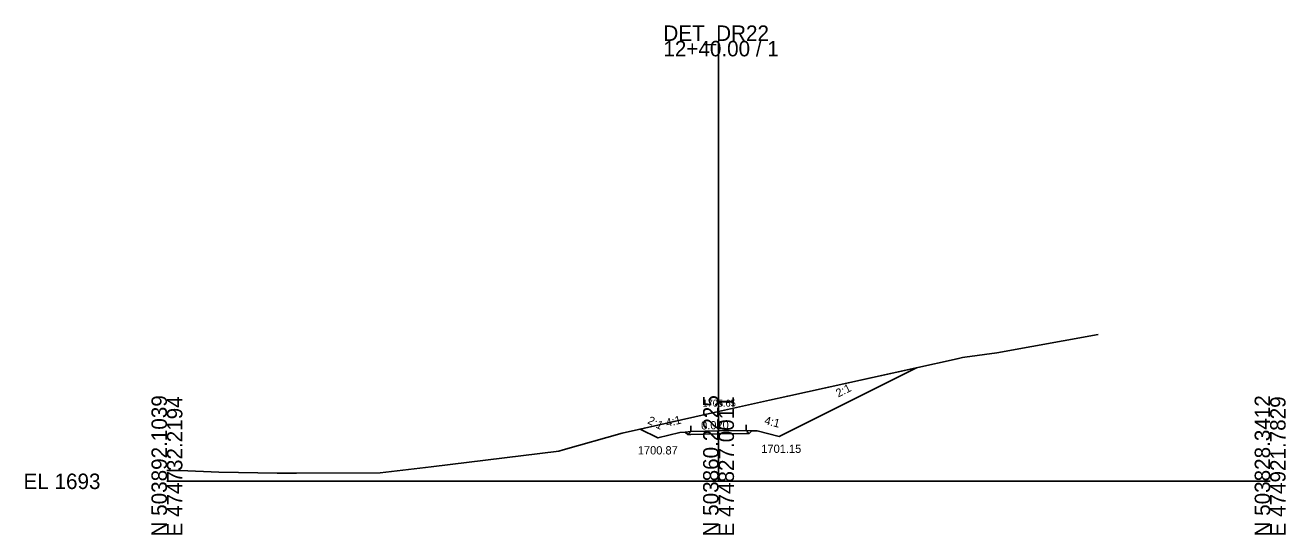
# Model space of a CAD drawing. Extents: x -26 to 1203, y -10 to 9633.
# Drawn here: x -25.7 to 202.8, y 5990.3 to 6082.7 of the extents above; entities that cross this region are included whole.
import ezdxf

# ---------------------------------------------------------------- set-up
doc = ezdxf.new("R2010")
doc.units = 0
for name, color, linetype in [('Exist Cross Section Cell', 7, 'Continuous'), ('Exist XS Center Line Elevation Label', 7, 'Continuous'), ('Exist XS Ground Line', 7, 'Continuous'), ('Prop XS Ditch Slope Text', 7, 'Continuous'), ('Prop XS Ditch Standard Text', 7, 'Continuous'), ('Prop XS Earthwork Shape', 7, 'Continuous'), ('Prop XS EOT Tick Mark', 7, 'Continuous'), ('Prop XS Finish Grade', 7, 'Continuous'), ('Prop XS Finish Grade Earthwork', 7, 'Continuous'), ('Prop XS Finish Grade Pavement', 7, 'Continuous'), ('Prop XS Pvmt Edge Slope', 7, 'Continuous'), ('Prop XS SE Text', 7, 'Continuous'), ('Prop XS Shoulder Borrow Shape', 7, 'Continuous'), ('Prop XS Side Slope Text', 7, 'Continuous'), ('Prop XS Subgrade Earthwork', 7, 'Continuous')]:
    doc.layers.add(name, color=color, linetype=linetype)

msp = doc.modelspace()

# ---------------------------------------------------------------- linework, layer by layer
at = {"layer": 'Exist Cross Section Cell'}
for p, q in [((100, 6000), (100, 6079.84)), ((0, 6000), (100, 6000)), ((100, 6000), (200, 6000))]:
    msp.add_line(p, q, dxfattribs=at)
at = {"layer": 'Exist XS Ground Line'}
msp.add_lwpolyline([(0, 6001.97), (2.41, 6001.96), (9.39, 6001.64), (12.96, 6001.6), (20, 6001.45), (22.63, 6001.47), (23.51, 6001.47), (38.65, 6001.53), (47.89, 6002.61), (71.03, 6005.44), (71.81, 6005.71), (82.51, 6008.71), (86.55, 6009.66), (100, 6012.65), (109.26, 6014.71), (112.55, 6015.44), (143.26, 6022.23), (144.23, 6022.43), (144.67, 6022.49), (150.43, 6023.29), (168.83, 6026.61)], dxfattribs=at)
at = {"layer": 'Prop XS Earthwork Shape'}
msp.add_lwpolyline([(105, 6008.68), (100, 6008.58), (95, 6008.48), (94.45, 6008.47), (93.98, 6008.94), (93, 6008.87), (89, 6007.87), (85.77, 6009.48), (86.55, 6009.66), (100, 6012.65), (109.26, 6014.71), (112.55, 6015.44), (135.91, 6020.6), (111, 6008.15), (107, 6009.15), (106.02, 6009.18), (105.53, 6008.69)], close=True, dxfattribs=at)
at = {"layer": 'Prop XS EOT Tick Mark'}
for p, q in [((95, 6009.03), (95, 6010.03)), ((105, 6009.23), (105, 6010.23))]:
    msp.add_line(p, q, dxfattribs=at)
at = {"layer": 'Prop XS Finish Grade'}
for p, q in [((95, 6009.03), (93.98, 6008.94)), ((105, 6009.23), (106.02, 6009.18))]:
    msp.add_line(p, q, dxfattribs=at)
at = {"layer": 'Prop XS Finish Grade Earthwork'}
for p, q in [((111, 6008.15), (135.91, 6020.6)), ((89, 6007.87), (85.77, 6009.48)), ((93, 6008.87), (89, 6007.87)), ((93.98, 6008.94), (93, 6008.87)), ((106.02, 6009.18), (107, 6009.15)), ((107, 6009.15), (111, 6008.15))]:
    msp.add_line(p, q, dxfattribs=at)
at = {"layer": 'Prop XS Finish Grade Pavement'}
for p, q in [((95, 6009.03), (100, 6009.13)), ((100, 6009.13), (105, 6009.23))]:
    msp.add_line(p, q, dxfattribs=at)
at = {"layer": 'Prop XS Pvmt Edge Slope'}
for p, q in [((95, 6009.03), (94.45, 6008.47)), ((105, 6009.23), (105.53, 6008.69))]:
    msp.add_line(p, q, dxfattribs=at)
at = {"layer": 'Prop XS Shoulder Borrow Shape'}
for points in [[(95, 6009.03), (93.98, 6008.94), (94.45, 6008.47)], [(105, 6009.23), (106.02, 6009.18), (105.53, 6008.69)]]:
    msp.add_lwpolyline(points, close=True, dxfattribs=at)
at = {"layer": 'Prop XS Subgrade Earthwork'}
for p, q in [((94.45, 6008.47), (93.98, 6008.94)), ((95, 6008.48), (94.45, 6008.47)), ((100, 6008.58), (95, 6008.48)), ((105, 6008.68), (100, 6008.58)), ((105, 6008.68), (105.53, 6008.69)), ((105.53, 6008.69), (106.02, 6009.18))]:
    msp.add_line(p, q, dxfattribs=at)

# ---------------------------------------------------------------- texts
at = {"layer": 'Exist Cross Section Cell'}
for s, p in [('DET_DR22', (90, 6079.84)), ('12+40.00 / 1', (90, 6077.04)), ('EL 1693', (-26, 5998.6))]:
    msp.add_text(s, height=2.8, dxfattribs=at).set_placement(p)
for s, p in [('N 503892.1039', (0, 5990)), ('E 474732.2194', (2.8, 5990)), ('N 503860.2225', (100, 5990)), ('E 474827.0011', (102.8, 5990)), ('N 503828.3412', (200, 5990)), ('E 474921.7829', (202.8, 5990))]:
    msp.add_text(s, height=2.8, rotation=90, dxfattribs=at).set_placement(p)
at = {"layer": 'Exist XS Center Line Elevation Label'}
msp.add_text('1705.65', height=1.25, dxfattribs=at).set_placement((97.09, 6013.54))
at = {"layer": 'Prop XS Ditch Slope Text'}
for rotation, p in [(14.0362, (90.64, 6009.82)), (345.9638, (108.21, 6010.39))]:
    msp.add_text('4:1', height=1.5, rotation=rotation, dxfattribs=at).set_placement(p)
at = {"layer": 'Prop XS Ditch Standard Text'}
for s, p in [('1700.87', (85.36, 6004.87)), ('1701.15', (107.75, 6005.15))]:
    msp.add_text(s, height=1.5, dxfattribs=at).set_placement(p)
at = {"layer": 'Prop XS SE Text'}
msp.add_text('0.020', height=1.5, rotation=1.1458, dxfattribs=at).set_placement((96.85, 6009.38))
at = {"layer": 'Prop XS Side Slope Text'}
for rotation, p in [(26.5651, (121.72, 6015.18)), (333.4349, (86.99, 6010.55))]:
    msp.add_text('2:1', height=1.5, rotation=rotation, dxfattribs=at).set_placement(p)

doc.saveas('drawing.dxf')
